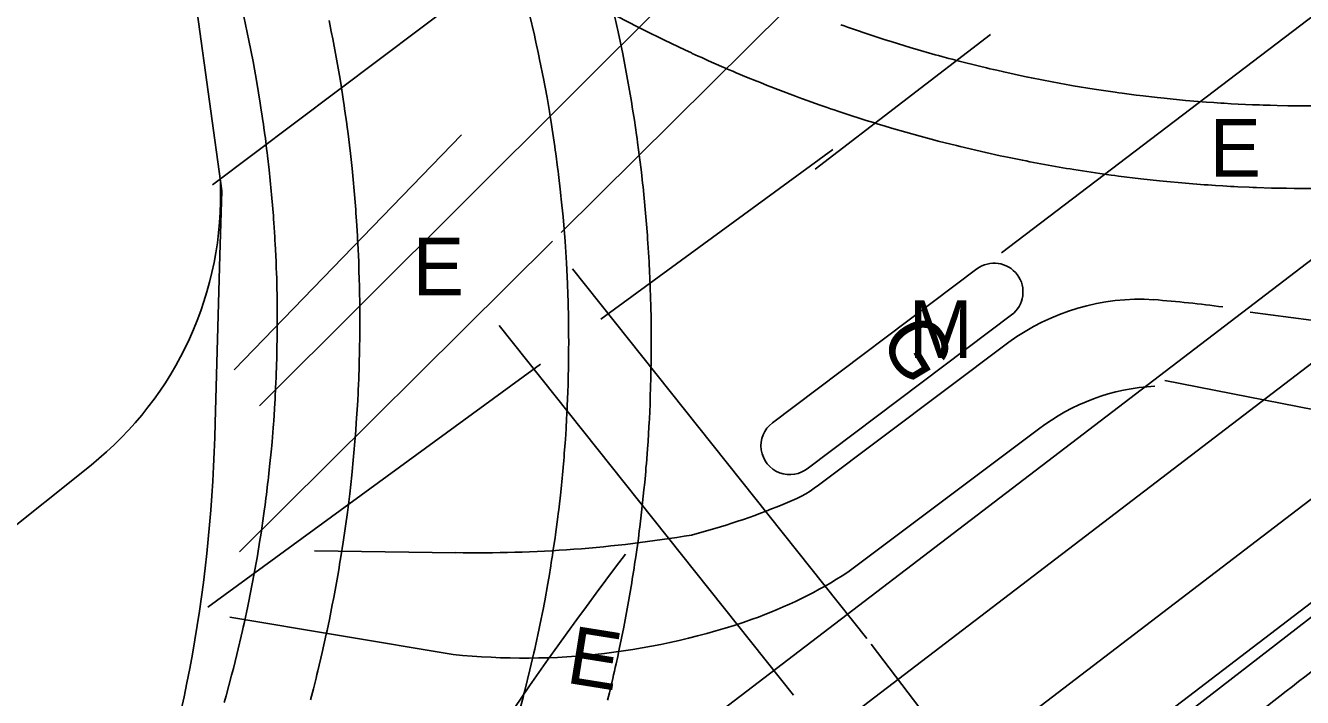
# Model space of a CAD drawing. Extents: x 81617 to 82144, y 454649 to 455150.
# Drawn here: x 81913.46 to 81935.65, y 454969.8 to 454981.48 of the extents above; entities that cross this region are included whole.
import ezdxf

# ---------------------------------------------------------------- set-up
doc = ezdxf.new("R2010")
doc.units = 0
for name, color, linetype in [('B-WE-OG-TOPOGRAFIE-G', 7, 'Continuous'), ('B-WE-VW-MARKERING-G', 7, 'Continuous'), ('N-OI-KL-VRI_KABELGEUL-G', 7, 'Continuous')]:
    doc.layers.add(name, color=color, linetype=linetype)

msp = doc.modelspace()

# ---------------------------------------------------------------- linework, layer by layer
at = {"layer": 'B-WE-OG-TOPOGRAFIE-G'}
for p, q in [((81916.836, 454977.482), (81916.751, 454974.573)), ((81926.436, 454974.576), (81929.99, 454977.25)), ((81927.06, 454973.794), (81930.591, 454976.451)), ((81909.611, 454969.854), (81914.596, 454973.843))]:
    msp.add_line(p, q, dxfattribs=at)
for points in [[(81873.49, 454927.861), (81874.235, 454928.464), (81874.684, 454928.824), (81874.834, 454928.943), (81875.133, 454929.183), (81876.035, 454929.897), (81876.336, 454930.134), (81876.944, 454930.61), (81877.553, 454931.084), (81877.859, 454931.32), (81878.164, 454931.557), (81879.083, 454932.264), (81879.697, 454932.734), (81880.618, 454933.44), (81881.483, 454934.1), (82053.484, 455065.539)], [(82052.863, 455062.717), (81907.219, 454951.42), (81881.918, 454932.086), (81881.368, 454931.665), (81879.897, 454930.54), (81879.014, 454929.861), (81878.133, 454929.178), (81876.818, 454928.147), (81876.529, 454927.916), (81876.383, 454927.802), (81875.945, 454927.452), (81875.222, 454926.872), (81874.931, 454926.636), (81874.646, 454926.404), (81874.501, 454926.287), (81873.923, 454925.815), (81873.138, 454925.168), (81872.64, 454924.754), (81871.896, 454924.132), (81871.4, 454923.716), (81870.675, 454923.104)], [(82053.734, 455061.577), (81908.09, 454950.28), (81882.79, 454930.946), (81882.24, 454930.525), (81880.77, 454929.401), (81879.891, 454928.725), (81879.015, 454928.046), (81877.708, 454927.021), (81877.419, 454926.791), (81877.274, 454926.677), (81876.842, 454926.332), (81876.122, 454925.754), (81875.835, 454925.522), (81875.549, 454925.289), (81875.405, 454925.173), (81874.834, 454924.706), (81874.053, 454924.062), (81873.558, 454923.651), (81872.817, 454923.032), (81872.324, 454922.618), (81871.758, 454922.14)], [(81901.778, 454951.416), (81947.621, 454986.447), (81958.806, 454994.995), (81973.12, 455005.933)], [(81915.753, 454984.345), (81916.38, 454982.031), (81916.438, 454981.711), (81916.869, 454978.605), (81916.836, 454977.482)], [(81917.832, 454976.209), (81917.832, 454976.516), (81917.83, 454976.639), (81917.83, 454976.701), (81917.828, 454976.823), (81917.826, 454976.885), (81917.825, 454976.946), (81917.823, 454977.008), (81917.822, 454977.069), (81917.818, 454977.192), (81917.815, 454977.254), (81917.811, 454977.376), (81917.796, 454977.683), (81917.792, 454977.745), (81917.789, 454977.806), (81917.773, 454978.052), (81917.768, 454978.113), (81917.764, 454978.174), (81917.739, 454978.48), (81917.733, 454978.542), (81917.728, 454978.603), (81917.71, 454978.786), (81917.691, 454978.97), (81917.663, 454979.214), (81917.655, 454979.275), (81917.648, 454979.336), (81917.64, 454979.397), (81917.633, 454979.458), (81917.625, 454979.519), (81917.616, 454979.58), (81917.6, 454979.702), (81917.591, 454979.763), (81917.583, 454979.824), (81917.565, 454979.945), (81917.555, 454980.006), (81917.537, 454980.128), (81917.477, 454980.491), (81917.411, 454980.854), (81917.34, 454981.216), (81917.25, 454981.637)], [(81922.216, 454981.669), (81922.3, 454981.31), (81922.313, 454981.25), (81922.327, 454981.19), (81922.366, 454981.009), (81922.378, 454980.949), (81922.391, 454980.889), (81922.463, 454980.527), (81922.474, 454980.467), (81922.486, 454980.407), (81922.519, 454980.225), (81922.561, 454979.983), (81922.581, 454979.862), (81922.59, 454979.801), (81922.61, 454979.68)], [(81923.7, 454981.626), (81923.756, 454981.371), (81923.835, 454980.989), (81923.847, 454980.925), (81923.86, 454980.861), (81923.92, 454980.541), (81923.931, 454980.477), (81923.943, 454980.413), (81923.987, 454980.156), (81924.007, 454980.028), (81924.018, 454979.964)], [(81929.003, 454979.555), (81928.752, 454979.625), (81928.502, 454979.697), (81928.377, 454979.735), (81928.315, 454979.753), (81928.253, 454979.772), (81928.191, 454979.792), (81928.066, 454979.83), (81927.694, 454979.95), (81927.571, 454979.992), (81927.509, 454980.012), (81927.447, 454980.033), (81927.386, 454980.055), (81927.263, 454980.097), (81926.956, 454980.207), (81926.895, 454980.23), (81926.834, 454980.252), (81926.53, 454980.367), (81926.408, 454980.415), (81926.347, 454980.438), (81926.226, 454980.486), (81926.166, 454980.511), (81925.985, 454980.584), (81925.805, 454980.659), (81925.745, 454980.685), (81925.685, 454980.71), (81925.327, 454980.866), (81925.208, 454980.92), (81925.148, 454980.946), (81925.041, 454980.995), (81925.03, 454981.001), (81924.912, 454981.055), (81924.559, 454981.223), (81924.209, 454981.396), (81924.092, 454981.455), (81923.746, 454981.635)], [(81919.266, 454976.135), (81919.267, 454976.2), (81919.267, 454976.526), (81919.265, 454976.656), (81919.265, 454976.721), (81919.263, 454976.786), (81919.261, 454976.916), (81919.259, 454976.982), (81919.258, 454977.047), (81919.252, 454977.242), (81919.249, 454977.307), (81919.247, 454977.372), (81919.232, 454977.697), (81919.228, 454977.762), (81919.225, 454977.827), (81919.209, 454978.087), (81919.199, 454978.217), (81919.195, 454978.282), (81919.19, 454978.347), (81919.184, 454978.412), (81919.174, 454978.541), (81919.144, 454978.866), (81919.137, 454978.93), (81919.131, 454978.995), (81919.103, 454979.254), (81919.056, 454979.642), (81919.047, 454979.706), (81919.039, 454979.771), (81919.003, 454980.029), (81918.993, 454980.093), (81918.984, 454980.158), (81918.934, 454980.479), (81918.912, 454980.608), (81918.902, 454980.672), (81918.891, 454980.736), (81918.879, 454980.8), (81918.868, 454980.864), (81918.856, 454980.928), (81918.845, 454980.993), (81918.797, 454981.248), (81918.771, 454981.376), (81918.759, 454981.44), (81918.733, 454981.568)], [(81929.381, 454980.939), (81929.322, 454980.956), (81929.263, 454980.972), (81929.204, 454980.989), (81928.967, 454981.056), (81928.908, 454981.074), (81928.849, 454981.091), (81928.497, 454981.199), (81928.438, 454981.218), (81928.379, 454981.236), (81928.204, 454981.293), (81927.738, 454981.451), (81927.68, 454981.472), (81927.622, 454981.492)], [(81935.393, 454980.085), (81935.208, 454980.088), (81935.085, 454980.092), (81935.024, 454980.093), (81934.962, 454980.095), (81934.901, 454980.098), (81934.778, 454980.102), (81934.409, 454980.12), (81934.287, 454980.128), (81934.225, 454980.131), (81934.164, 454980.135), (81934.103, 454980.14), (81933.98, 454980.148), (81933.612, 454980.178), (81933.245, 454980.214), (81933.184, 454980.221), (81933.123, 454980.227), (81932.878, 454980.255), (81932.817, 454980.263), (81932.756, 454980.27), (81932.512, 454980.302), (81932.452, 454980.311), (81932.391, 454980.319), (81932.026, 454980.373), (81931.662, 454980.433), (81931.601, 454980.444), (81931.54, 454980.454), (81931.299, 454980.498), (81930.936, 454980.569), (81930.876, 454980.582), (81930.816, 454980.594), (81930.455, 454980.672), (81930.336, 454980.7), (81930.276, 454980.713), (81930.216, 454980.727), (81930.156, 454980.742), (81930.036, 454980.77), (81929.679, 454980.86), (81929.56, 454980.892), (81929.5, 454980.907), (81929.381, 454980.939)], [(81935.946, 454980.082), (81935.577, 454980.082), (81935.393, 454980.085)], [(81924.018, 454979.964), (81924.038, 454979.835), (81924.075, 454979.577), (81924.085, 454979.513), (81924.093, 454979.448), (81924.111, 454979.319), (81924.159, 454978.932), (81924.173, 454978.802), (81924.181, 454978.738), (81924.187, 454978.673), (81924.201, 454978.543), (81924.207, 454978.479), (81924.214, 454978.414), (81924.226, 454978.284), (81924.231, 454978.219), (81924.243, 454978.09), (81924.263, 454977.83), (81924.267, 454977.765), (81924.272, 454977.7), (81924.292, 454977.375), (81924.295, 454977.31), (81924.299, 454977.245), (81924.308, 454977.05), (81924.31, 454976.985), (81924.313, 454976.92), (81924.323, 454976.595), (81924.324, 454976.53), (81924.326, 454976.465), (81924.33, 454976.204), (81924.33, 454976.074), (81924.331, 454976.009), (81924.331, 454975.944), (81924.33, 454975.879), (81924.33, 454975.749), (81924.324, 454975.358), (81924.314, 454975.033), (81924.311, 454974.968), (81924.309, 454974.903), (81924.297, 454974.643), (81924.293, 454974.578), (81924.29, 454974.513), (81924.274, 454974.253), (81924.269, 454974.188), (81924.265, 454974.123), (81924.245, 454973.863), (81924.239, 454973.798), (81924.234, 454973.733), (81924.216, 454973.539)], [(81922.61, 454979.68), (81922.655, 454979.376), (81922.663, 454979.315), (81922.672, 454979.254), (81922.704, 454979.01), (81922.711, 454978.949), (81922.719, 454978.888), (81922.754, 454978.583), (81922.76, 454978.522), (81922.767, 454978.461), (81922.797, 454978.155), (81922.832, 454977.726), (81922.856, 454977.358), (81922.874, 454976.99), (81922.876, 454976.928), (81922.879, 454976.867), (81922.887, 454976.621), (81922.888, 454976.56), (81922.89, 454976.498), (81922.895, 454976.191), (81922.895, 454976.068), (81922.896, 454976.006), (81922.896, 454975.945), (81922.895, 454975.884), (81922.895, 454975.761), (81922.893, 454975.638), (81922.893, 454975.576), (81922.891, 454975.515), (81922.889, 454975.392), (81922.887, 454975.33), (81922.886, 454975.269), (81922.88, 454975.085), (81922.877, 454975.023), (81922.875, 454974.962), (81922.872, 454974.9), (81922.87, 454974.839), (81922.864, 454974.716), (81922.86, 454974.655), (81922.857, 454974.594), (81922.853, 454974.532), (81922.85, 454974.471), (81922.838, 454974.287), (81922.833, 454974.226), (81922.829, 454974.164), (81922.819, 454974.042), (81922.815, 454973.98), (81922.809, 454973.919), (81922.799, 454973.797), (81922.787, 454973.674), (81922.782, 454973.613)], [(81935.37, 454978.65), (81935.24, 454978.652), (81935.174, 454978.654), (81935.109, 454978.655), (81934.849, 454978.663), (81934.784, 454978.666), (81934.719, 454978.668), (81934.524, 454978.677), (81934.459, 454978.681), (81934.394, 454978.684), (81934.329, 454978.688), (81934.263, 454978.691), (81934.133, 454978.699), (81934.069, 454978.704), (81934.004, 454978.708), (81933.939, 454978.713), (81933.874, 454978.717), (81933.679, 454978.732), (81933.614, 454978.738), (81933.549, 454978.743), (81933.29, 454978.767), (81933.225, 454978.774), (81933.16, 454978.78), (81932.836, 454978.815), (81932.449, 454978.863), (81932.384, 454978.872), (81932.319, 454978.88), (81932.126, 454978.907), (81931.675, 454978.976), (81931.611, 454978.987), (81931.547, 454978.997), (81931.29, 454979.041), (81931.226, 454979.053), (81931.162, 454979.064), (81930.906, 454979.112), (81930.842, 454979.125), (81930.778, 454979.137), (81930.523, 454979.189), (81930.459, 454979.203), (81930.395, 454979.216), (81930.141, 454979.272), (81929.697, 454979.376), (81929.634, 454979.392), (81929.318, 454979.471), (81929.255, 454979.488), (81929.192, 454979.504), (81929.003, 454979.555)], [(81935.956, 454978.647), (81935.63, 454978.647), (81935.565, 454978.648), (81935.5, 454978.648), (81935.37, 454978.65)], [(81917.038, 454970.191), (81917.053, 454970.251), (81917.069, 454970.31), (81917.129, 454970.549), (81917.228, 454970.967), (81917.241, 454971.027), (81917.255, 454971.087), (81917.32, 454971.388), (81917.344, 454971.508), (81917.357, 454971.568), (81917.404, 454971.81), (81917.426, 454971.931), (81917.438, 454971.991), (81917.449, 454972.051), (81917.459, 454972.112), (81917.481, 454972.233), (81917.531, 454972.536), (81917.54, 454972.597), (81917.55, 454972.658), (81917.595, 454972.962), (81917.611, 454973.084), (81917.62, 454973.145), (81917.636, 454973.266), (81917.643, 454973.327), (81917.651, 454973.388), (81917.665, 454973.511), (81917.673, 454973.572), (81917.68, 454973.633), (81917.686, 454973.694), (81917.7, 454973.816), (81917.73, 454974.122), (81917.735, 454974.183), (81917.741, 454974.244), (81917.761, 454974.489), (81917.765, 454974.551), (81917.77, 454974.612), (81917.79, 454974.919), (81917.793, 454974.98), (81917.797, 454975.041), (81917.809, 454975.287), (81917.811, 454975.348), (81917.814, 454975.41), (81917.824, 454975.717), (81917.825, 454975.779), (81917.827, 454975.84), (81917.831, 454976.086), (81917.831, 454976.147), (81917.832, 454976.209)], [(81918.409, 454969.764), (81918.426, 454969.827), (81918.442, 454969.89), (81918.459, 454969.953), (81918.507, 454970.142), (81918.522, 454970.206), (81918.538, 454970.269), (81918.613, 454970.586), (81918.684, 454970.903), (81918.697, 454970.967), (81918.738, 454971.158), (81918.751, 454971.222), (81918.763, 454971.286), (81918.789, 454971.413), (81918.813, 454971.541), (81918.826, 454971.605), (81918.837, 454971.669), (81918.861, 454971.797), (81918.872, 454971.862), (81918.884, 454971.926), (81918.906, 454972.054), (81918.916, 454972.118), (81918.938, 454972.247), (81918.978, 454972.504), (81919.051, 454973.02), (81919.091, 454973.343), (81919.127, 454973.666), (81919.133, 454973.731), (81919.14, 454973.796), (81919.146, 454973.861), (81919.153, 454973.925), (81919.165, 454974.055), (81919.17, 454974.12), (81919.176, 454974.185), (81919.186, 454974.314), (81919.192, 454974.379), (81919.196, 454974.444), (81919.206, 454974.574), (81919.23, 454974.964), (81919.236, 454975.094), (81919.24, 454975.159), (81919.242, 454975.224), (81919.248, 454975.354), (81919.25, 454975.419), (81919.253, 454975.484), (81919.257, 454975.615), (81919.258, 454975.68), (81919.26, 454975.745), (81919.261, 454975.81), (81919.263, 454975.875), (81919.266, 454976.07), (81919.266, 454976.135)], [(81939.478, 454974.048), (81923.575, 454961.742), (81923.877, 454961.345), (81919.157, 454957.774)], [(81922.782, 454973.613), (81922.776, 454973.552), (81922.769, 454973.491), (81922.757, 454973.369), (81922.722, 454973.063), (81922.714, 454973.002), (81922.707, 454972.941), (81922.667, 454972.636), (81922.658, 454972.576), (81922.65, 454972.515), (81922.623, 454972.332), (81922.613, 454972.272), (81922.604, 454972.211), (81922.594, 454972.15), (81922.585, 454972.089), (81922.555, 454971.908), (81922.544, 454971.847), (81922.534, 454971.786), (81922.479, 454971.484), (81922.467, 454971.424), (81922.456, 454971.363), (81922.396, 454971.062), (81922.383, 454971.002), (81922.319, 454970.701), (81922.305, 454970.641), (81922.292, 454970.581), (81922.222, 454970.282), (81922.133, 454969.924), (81922.117, 454969.865), (81922.102, 454969.805), (81922.006, 454969.449)], [(81924.216, 454973.539), (81924.204, 454973.409), (81924.162, 454973.021), (81924.131, 454972.763), (81924.122, 454972.698), (81924.106, 454972.569), (81924.061, 454972.247), (81924.041, 454972.118), (81924.032, 454972.053), (81924.012, 454971.925), (81924.001, 454971.861), (81923.991, 454971.796), (81923.925, 454971.411), (81923.853, 454971.027), (81923.775, 454970.645), (81923.747, 454970.517), (81923.72, 454970.39), (81923.705, 454970.327), (81923.691, 454970.263), (81923.676, 454970.2), (81923.662, 454970.136), (81923.602, 454969.883), (81923.57, 454969.757)], [(81916.908, 454969.717), (81916.942, 454969.835), (81917.038, 454970.191)]]:
    msp.add_lwpolyline(points, dxfattribs=at)
for centre, radius, start, end in [((81910.848, 454978.528), 6, 308.6669, 2.2469), ((81930.29, 454976.85), 0.5, 306.9581, 126.9581), ((81891.435, 454975.03), 25.32, 340.6848, 358.9647), ((81926.737, 454974.176), 0.5, 126.9581, 310.2452)]:
    msp.add_arc(centre, radius, start, end, dxfattribs=at)
at = {"layer": 'B-WE-VW-MARKERING-G'}
for p, q in [((81930.414, 454977.529), (81947.033, 454990.169)), ((81928.734, 454987.769), (81916.709, 454978.71)), ((81923.454, 454976.376), (81927.483, 454979.322)), ((81922.961, 454977.249), (81928.074, 454970.829)), ((81940.399, 454975.738), (81934.739, 454976.5)), ((81921.689, 454976.266), (81926.802, 454969.846)), ((81927.234, 454973.491), (81930.546, 454975.976)), ((81922.405, 454975.596), (81916.626, 454971.371)), ((81939.05, 454974.173), (81933.256, 454975.312)), ((81927.748, 454971.98), (81931.06, 454974.465)), ((81920.932, 454972.32), (81918.479, 454972.352)), ((81920.888, 454970.552), (81917.008, 454971.2))]:
    msp.add_line(p, q, dxfattribs=at)
for points in [[(81930.057, 454987.37), (81917.525, 454974.87)], [(81931.874, 454986.919), (81922.766, 454977.882)], [(81930.222, 454981.324), (81927.178, 454978.983)], [(81921.031, 454979.579), (81917.086, 454975.496)], [(81922.616, 454977.733), (81917.177, 454972.336)], [(81928.149, 454970.73), (81930.487, 454967.661)]]:
    msp.add_lwpolyline(points, dxfattribs=at)
for centre, radius, start, end in [((81932.826, 454972.869), 3.854, 86.4467, 126.274), ((81931.451, 454955.775), 21.003, 82.3065, 85.5941), ((81933.271, 454971.594), 3.624, 93.0211, 127.601), ((81925.829, 454975.364), 2.342, 289.6644, 306.8837), ((81922.063, 454984.096), 11.847, 284.5008, 292.6025), ((81921.315, 454994.768), 22.451, 269.0205, 279.523), ((81968.831, 454937.782), 56.668, 142.4843, 151.6344), ((81923.39, 454978.745), 8.047, 289.5611, 302.7929), ((81922.125, 454982.449), 11.961, 264.0626, 289.3304)]:
    msp.add_arc(centre, radius, start, end, dxfattribs=at)
at = {"layer": 'N-OI-KL-VRI_KABELGEUL-G'}
msp.add_open_spline([(81966.954, 454994.044), (81954.516, 454984.42), (81942.079, 454974.796), (81941.008, 454974.125), (81939.937, 454973.455), (81933.631, 454968.575), (81927.325, 454963.696), (81926.798, 454963.288), (81926.621, 454962.646), (81926.355, 454961.682), (81926.09, 454960.718), (81925.901, 454960.035), (81925.325, 454959.623), (81922.434, 454957.557), (81919.543, 454955.49), (81917.87, 454954.23), (81916.197, 454952.97), (81913.406, 454950.849), (81910.615, 454948.728), (81908.564, 454947.145), (81906.513, 454945.562), (81905.944, 454945.123), (81905.225, 454945.147), (81904.815, 454945.16), (81904.405, 454945.174), (81903.693, 454945.197), (81903.126, 454944.765), (81893.683, 454937.565), (81884.239, 454930.365), (81883.469, 454929.731), (81882.698, 454929.096), (81879.285, 454926.178), (81875.872, 454923.259), (81872.421, 454920.321), (81868.97, 454917.382), (81867.082, 454915.724), (81865.195, 454914.067), (81863.45, 454912.271), (81861.704, 454910.475), (81860.838, 454909.482), (81859.972, 454908.49), (81859.86, 454908.361), (81859.97, 454908.23), (81860.094, 454908.077), (81860.218, 454907.925), (81863.368, 454903.762), (81866.518, 454899.599), (81866.598, 454899.497), (81866.679, 454899.395)], degree=4, dxfattribs=at)

# ---------------------------------------------------------------- texts
at = {"layer": 'B-WE-OG-TOPOGRAFIE-G'}
for s, p in [('E', (81934.032, 454978.854)), ('E', (81920.186, 454976.79)), ('M', (81928.802, 454975.702)), ('M', (81928.802, 454975.702))]:
    msp.add_text(s, height=1, dxfattribs=at).set_placement(p)
for s, rotation, p in [('G', 301.0754, (81928.272, 454976.05)), ('E', 350.9055, (81922.828, 454970.064))]:
    msp.add_text(s, height=1, rotation=rotation, dxfattribs=at).set_placement(p)

doc.saveas('drawing.dxf')
